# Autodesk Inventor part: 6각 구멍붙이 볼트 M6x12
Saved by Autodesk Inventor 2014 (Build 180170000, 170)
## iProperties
Created: 2025-06
Part Number: 6각 구멍붙이 볼트 M6x12
Material: 일반
Document SubType Name: Modeling
Designer: dg
Density: 1 g/cm^3
Appearance: 기본값
Author: dg
Author: jhkim
Description: 6각머리 태핑 나사
Creation Date: 2025-05-23
Sending System: Autodesk Inventor 2026
Preprocessor: ST-DEVELOPER v20.1
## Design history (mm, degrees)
node "6각 구멍붙이 볼트 M6x121"
body "Solid1"
node "기준1"
